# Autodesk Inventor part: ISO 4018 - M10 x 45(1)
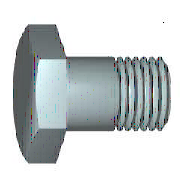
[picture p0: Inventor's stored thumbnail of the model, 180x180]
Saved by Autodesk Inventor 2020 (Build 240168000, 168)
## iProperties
Created: 2019-01
Part Number: ISO 4018 - M10 x 45(1)
Material: Ocel
Description: Šrouby se šestihrannou hlavou se závitem k hlavě. Výrobní třída C
Document SubType Name: Modeling
Standard: ISO 4018
Designer: doma
Standard Revision: Fourth edition 2011-04-01
Standards Organization: ISO
Language: cs-CZ
Size Designation: M10 x 45
Categories: <MemberInstance><Categories><Category DisplayName="Spojovací materiál" InternalName="e4da775c-781d-43d5-af7c-5136215cf5a6" Mnemonic="FSTN"><Category DisplayName
Density: 7.85 g/cm^3
Appearance: Plech
IsCustomPart: 0
Author: doma
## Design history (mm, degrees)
node "WorkPlane1"
node "WorkPoint1"
node "MSC_A1"
node "MSC_PF1"
node "MSC_PT1"
body "Solid1"
node "Náčrt1"
sketch "Náčrt2"
  geometry: L1 (-8, 4.619)-(-8, -4.619); L2 (0, 9.237)-(-8, 4.619); L3 (8, 4.619)-(0, 9.237); L4 (8, -4.619)-(8, 4.619); L5 (0, -9.237)-(8, -4.619); L6 (-8, -4.619)-(0, -9.237); C1 r 8 at (0, 0); 1 further point
  constraints: 12 end point, 6 tangent, 2 parallel, 2 vertical, 1 centre point
  dimensions: "d1" = 16 diameter of C1 (= ParS); "d29" = 0 distance of point (0, 0) C1.centre; "d30" = 0 distance of C1.centre point (0, 0)
extrude "Vysunutí1" new body sketch "Náčrt2" distance "d6" = 6.4 (= ParK); taper "d7" = 0 deg
revolve "Rotace1" stored, may be unused: angle "d14" = 360 deg
revolve "Rotace2" stored, may be unused: angle "d21" = 360 deg
chamfer "Zkosení1" distance "d22" = 0.75 (= 0.5 x PTC); stored, may be unused: second distance "d23" = 0.75 (= 0.5 x PTC), angle "d39" = 45 deg
fillet "Zaoblení1" dims "d24" = 0.4 (= r)
feature "Závit1" dims "d32" = 0, "b" = 42 (= NLG - 2 x PTC)
sketch "Náčrt3"
  geometry: L1 (8, 6.4)-(9.337, 6.4); L2 (9.337, 5.628)-(8, 6.4); L3 (9.337, 6.4)-(9.337, 5.628); L4 (0, -1.28)-(0, 7.68) reference; L5 (9.237, 0)-(9.237, 6.4) reference
  constraints: 6 end point, 1 horizontal, 1 vertical
  dimensions: "d25" = 0.1 distance between parallel lines of L5 L3; "d26" = 0 distance from line of L5.end L1; "d27" = 60 deg angle of L3 L2; "d28" = 8 distance from line of L4 L1.start (= 0.5 x ParS)
sketch "Náčrt4"
  geometry: L1 (0, -45)-(0, 0); L2 (-5, -45)-(0, -45); L3 (-5, 0)-(-5, -45); L4 (0, 0)-(-5, 0); L5 (0, -45)-(0, 0); L6 (-6, 0)-(1, 0) reference; L7 (0, -54)-(0, 9) reference
  constraints: 10 end point, 2 horizontal, 2 vertical
  dimensions: "d18" = 5 distance of L1.start L2.start (= 0.5 x NND); "d20" = 45 distance of L3.start L2.start (= NLG); "d33" = 0 distance between parallel lines of L7 L1; "d34" = 0 distance between parallel lines of L6 L4
other parameters: "NLG" = 45 [user parameter; used in 2 equation terms], "PTC" = 1.5 [user parameter; used in 3 equation terms], "ParK" = 6.4 [user parameter; used in 1 equation term], "ParS" = 16 [user parameter; used in 3 equation terms], "msp_es" = 9.23788 (= 0.577367 x ParS) [user parameter], "r" = 0.4 [user parameter; used in 1 equation term], "d2" = 15 (derived), "d4" = 17.32102 (derived), "d8" = 15 (derived), "d10" = 0 (derived), "d12" = 30 deg (derived), "d15" = 0 (derived), "d37" = 0, "d38" = 0, "d40" = 0, "d41" = 0, "d42" = 0
